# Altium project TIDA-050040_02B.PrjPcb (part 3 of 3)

## Sheet TIDA-050040_PwrSupplies.SchDoc: MCU Power 2
size 431 x 279 mm; Date: Not shown in title block; ApprovedBy: Not shown in title block; CheckedBy: Not shown in title block; Author: Not shown in title block; CompanyName: Not shown in title block; DrawnBy: Kerry Murphy; Engineer: Not shown in title block; Organization: Not shown in title block; Address1: Not shown in title block; Address2: Not shown in title block; Address3: Not shown in title block; Address4: Not shown in title block; DocumentNumber: 9; Revision: Use project parameter SCH_Rev; SheetNumber: 9; SheetTotal: 10; PageSetup: Record=PageOptions¦CenterHorizontal=True¦CenterVertical=True¦PrintScale=1.00¦XCorrection=1.00¦YCorrection=1.00¦PrintKind=0¦BorderSize=5000000¦LeftOffset=0¦BottomOffset=0¦Orientation=2¦PaperLength=1000¦PaperWidth=1000¦Scale=100¦PaperSource=15¦PrintQuality=600¦MediaType=1¦DitherType=10¦PaperKind=Letter¦PrintScaleMode=1
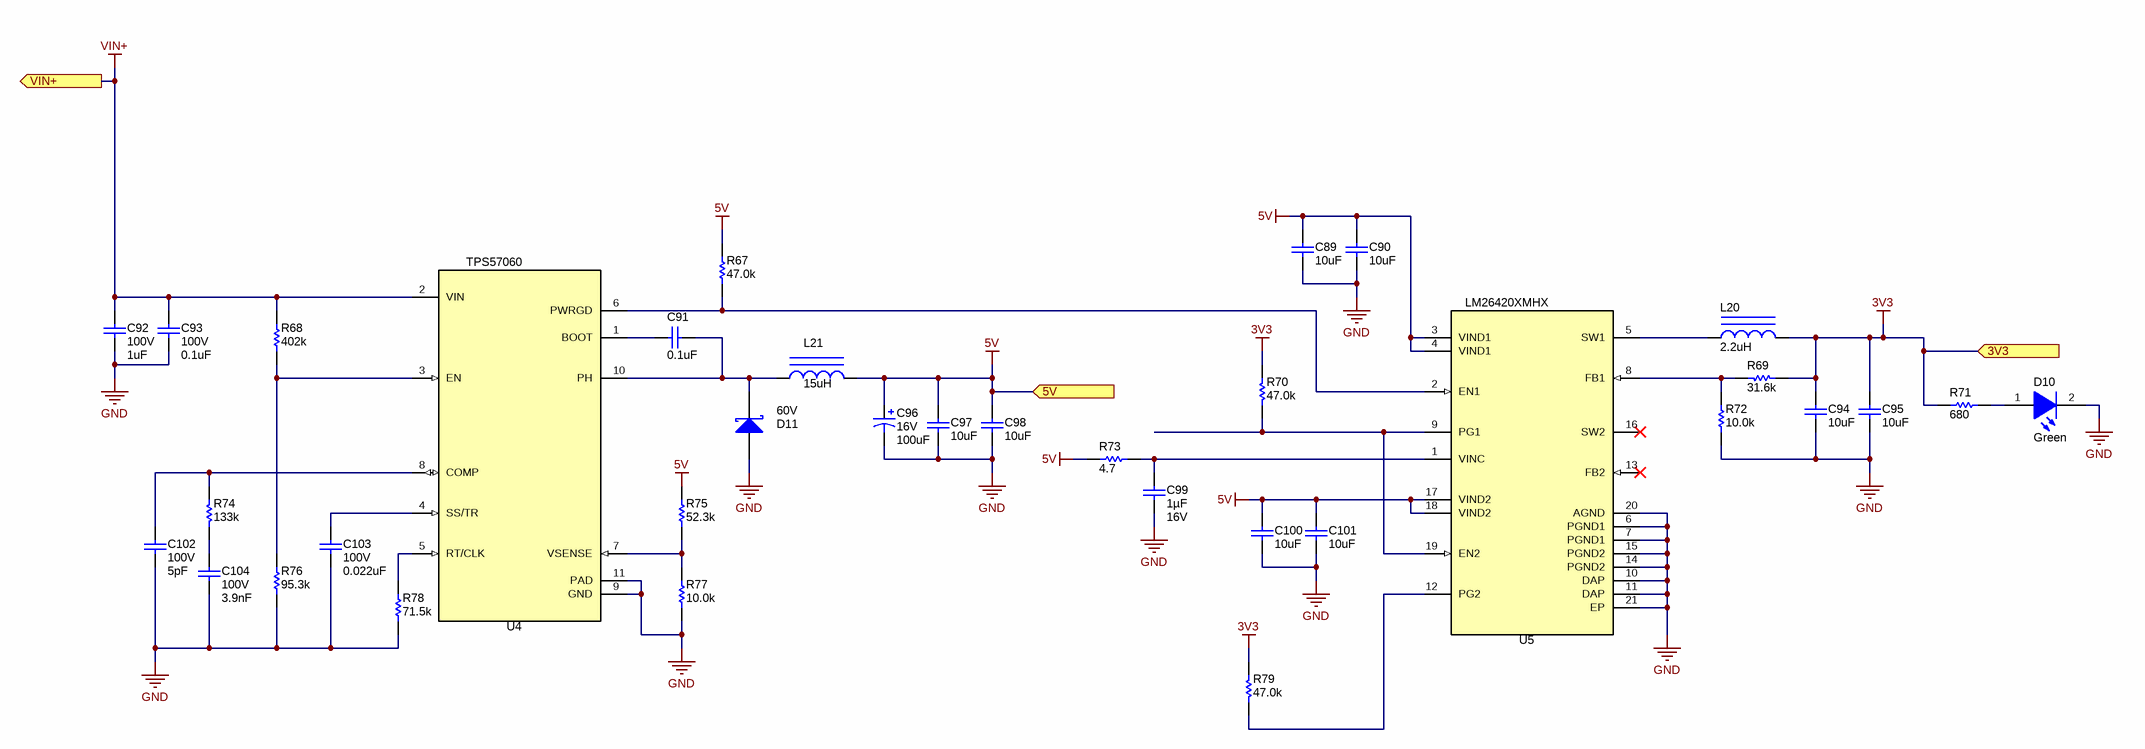
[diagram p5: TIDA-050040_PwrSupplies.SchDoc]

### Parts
C89  ValueDisplayed: 10uF  [1206_180]  (hidden comment: Capacitor)
C90  ValueDisplayed: 10uF  [1206_180]  (hidden comment: Capacitor)
C91  ValueDisplayed: 0.1uF  [0603_HV]  (hidden comment: Capacitor)
C92  VDC_V: 100V  ValueDisplayed: 1uF  [0805_HV]  (hidden comment: CGA4J3X7S2A105K125AB)
C93  VDC_V: 100V  ValueDisplayed: 0.1uF  [0805_HV]  (hidden comment: CGA4J2X7R2A104K125AA)
C94  ValueDisplayed: 10uF  [1206_180]  (hidden comment: Capacitor)
C95  ValueDisplayed: 10uF  [1206_180]  (hidden comment: Capacitor)
C96  VDC_V: 16V  ValueDisplayed: 100uF  [SM_RADIAL_D]  (hidden comment: EEEFP1C101AP)
C97  ValueDisplayed: 10uF  [1206_180]  (hidden comment: Capacitor)
C98  ValueDisplayed: 10uF  [1206_180]  (hidden comment: Capacitor)
C99  Cap_F: 1µF  VDC_V: 16V  [0603]  (hidden comment: EMK107B7105KAHT)
C100  ValueDisplayed: 10uF  [1206_180]  (hidden comment: Capacitor)
C101  ValueDisplayed: 10uF  [1206_180]  (hidden comment: Capacitor)
C102  VDC_V: 100V  ValueDisplayed: 5pF  [0402]  (hidden comment: GRM1555C2A5R0CA01D)
C103  VDC_V: 100V  ValueDisplayed: 0.022uF  [0603]  (hidden comment: CGA3E2X7R2A223K080AA)
C104  VDC_V: 100V  Cap_F: 3.9nF  [0603]  (hidden comment: 06031C392JAT2A)
D10  value Green  [LG_R971_Green]  (hidden comment: LED)
D11  value 60V  [SMA]  (hidden comment: DIODE_SCHOTTKY)
L20  ValueDisplayed: 2.2uH  [LPS3010]  (hidden comment: LPS3010-222MLB)
L21  ValueDisplayed: 15uH  [XAL4040]  (hidden comment: Inductor_Iron)
R67  ValueDisplayed: 47.0k  [0603_HV]  (hidden comment: Resistor)
R68  ValueDisplayed: 402k  [0603]  (hidden comment: ERJ-3EKF4023V)
R69  ValueDisplayed: 31.6k  [0603_HV]  (hidden comment: Resistor)
R70  ValueDisplayed: 47.0k  [0603_HV]  (hidden comment: Resistor)
R71  ValueDisplayed: 680  [0603_HV]  (hidden comment: Resistor)
R72  ValueDisplayed: 10.0k  [0603_HV]  (hidden comment: Resistor)
R73  ValueDisplayed: 4.7  [0603_HV]  (hidden comment: Resistor)
R74  ValueDisplayed: 133k  [0603_HV]  (hidden comment: Resistor)
R75  ValueDisplayed: 52.3k  [0603_HV]  (hidden comment: Resistor)
R76  ValueDisplayed: 95.3k  [0603_HV]  (hidden comment: Resistor)
R77  ValueDisplayed: 10.0k  [0603_HV]  (hidden comment: Resistor)
R78  ValueDisplayed: 71.5k  [0603]  (hidden comment: CRCW060371K5FKEA)
R79  ValueDisplayed: 47.0k  [0603_HV]  (hidden comment: Resistor)
U4  TPS57060  [DGQ0010D_N]
U5  LM26420XMHX  [PWP0020A_N]

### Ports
3V3, 5V, VIN+

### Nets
3V3: C94.1 C95.1 L20.2 R69.1 R70.2 R71.2 R79.2 ; port 3V3
5V: C89.1 C90.1 C96.1(+) C97.1 C98.1 C100.1 C101.1 L21.2 R67.2 R73.1 R75.2 U5.3(VIND1) U5.4(VIND1) U5.17(VIND2) U5.18(VIND2) ; port 5V
GND: C89.2 C90.2 C92.2 C93.2 C94.2 C95.2 C96.2(-) C97.2 C98.2 C99.2 C100.2 C101.2 C102.2 C103.2 C104.2 D10.2(K) D11.2(A) R72.1 R76.1 R77.1 R78.1 U4.9(GND) U4.11(PAD) U5.6(PGND1) U5.7(PGND1) U5.10(DAP) U5.11(DAP) U5.14(PGND2) U5.15(PGND2) U5.20(AGND) U5.21(EP)
VIN+: C92.1 C93.1 R68.2 U4.2(VIN) ; port VIN+  [project net VIN]
NetC91_1: C91.1 U4.1(BOOT)
NetC91_2: C91.2 D11.1(K) L21.1 U4.10(PH)
NetC99_1: C99.1 R73.2 U5.1(VINC)
NetC102_1: C102.1 R74.2 U4.8(COMP)
NetC103_1: C103.1 U4.4(SS/TR)
NetC104_1: C104.1 R74.1
NetD10_1: D10.1(A) R71.1
NetL20_1: L20.1 U5.5(SW1)
NetR67_1: R67.1 U4.6(PWRGD) U5.2(EN1)
NetR68_1: R68.1 R76.2 U4.3(EN)
NetR69_2: R69.2 R72.2 U5.8(FB1)
NetR70_1: R70.1 U5.9(PG1) U5.19(EN2)
NetR75_1: R75.1 R77.2 U4.7(VSENSE)
NetR78_2: R78.2 U4.5(RT/CLK)
NetR79_1: R79.1 U5.12(PG2)

Not connected (* = marked no-connect by the designer): U5 13(FB2)* 16(SW2)*

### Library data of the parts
C89 C90 C94 C95 C97 C98 C100 C101 = CMP-0008965-2: CAP, CERM, 10 uF, 25 V, +/- 10%, X7R, 1206; PartNumber: GRM31CR71E106KA12L; Manufacturer: MuRata; Polarized: N; Value: 10uF; U/M: EA; Cap_F: 10µF; Value1: Unknown; VDC_V: 25V; TaMin_C: -55°C; TaMax_C: 125°C; Cap_Case: 2220; SizeArea_mm2: 5.12; SizeAreaWB_mm2: 10.92; SizeX_mm: 3.2; SizeY_mm: 1.6; SizeZ_mm: 1.8; AEC Category: Q200
C91 = CMP-0007469-4: CAP, CERM, 0.1 uF, 100 V, +/- 10%, X7R, 0603; PartNumber: GRM188R72A104KA35D; Manufacturer: MuRata; Polarized: N; Value: 0.1uF; U/M: EA; Cap_F: 100nF; Value1: Unknown; VDC_V: 100V; TaMin_C: -55°C; TaMax_C: 125°C; Cap_Case: 0603; SizeArea_mm2: 1.28; SizeAreaWB_mm2: 4.68; SizeX_mm: 1.6; SizeY_mm: 0.8; SizeZ_mm: 1; AEC Category: Q200
C92 = CMP-0007980-2: CAP, CERM, 1 uF, 100 V, +/- 10%, X7S, AEC-Q200 Grade 1, 0805; Manufacturer: TDK; TaMin_C: -55°C; ESR_ohm: 8.255m; Polarized: N; SizeAreaWB_mm2: 6.75; Value1: 0.008255 ohm; U/M: EA; Value: 1uF; TaMax_C: 125°C; SizeZ_mm: 1.45; SizeX_mm: 2; SizeY_mm: 1.25; Cap_Case: 0805; SizeArea_mm2: 2.5; AEC Qualified: Y; Cap_F: 1µF; IRMS_A: 2.27442A; AEC Grade: 1; AEC Category: Q200
C93 = CMP-0007969-2: CAP, CERM, 0.1 uF, 100 V, +/- 10%, X7R, AEC-Q200 Grade 1, 0805; Manufacturer: TDK; TaMin_C: -55°C; ESR_ohm: 0.020726; Polarized: N; SizeAreaWB_mm2: 6.75; Value1: 0.020726 ohm; U/M: EA; Value: 0.1uF; TaMax_C: 125°C; SizeZ_mm: 1.45; SizeX_mm: 2; SizeY_mm: 1.25; Cap_Case: 0805; SizeArea_mm2: 2.5; CompType: Capacitor; AEC Qualified: Y; Cap_F: 100nF; IRMS_A: 1.456A; AEC Grade: 1; AEC Category: Q200
C96 = CMP-0010733-1: CAP, AL, 100 uF, 16 V, +/- 20%, 0.26 ohm, AEC-Q200 Grade 2, SMD; Manufacturer: Panasonic; TaMin_C: -55°C; ESR_ohm: 2.6d; Polarized: Y; SizeAreaWB_mm2: 84.28; U/M: EA; Value: 100uF; TaMax_C: 125°C; SizeZ_mm: 5.4; SizeX_mm: 7.8; SizeY_mm: 6.6; Cap_Case: D; SizeArea_mm2: 51.48; CompType: Capacitor; Cap_F: 100µF; AEC Grade: 2; AEC Category: Q200
C99 = CMP-0080104-1: CAP, CERM, 1 µF, 16 V,+/- 10%, X7R, AEC-Q200 Grade 1, 0603; Manufacturer: Taiyo Yuden; SizeAreaWB_mm2: 4.68; SizeArea_mm2: 1.28; AEC Qualified: Y; AEC Category: Q200; Value: 1uF; TaMax_C: 125°C; SizeZ_mm: 1; Polarized: N; TaMin_C: -55°C; SizeY_mm: 0.8; U/M: EA; CompType: Capacitor; SizeX_mm: 1.6
C102 = CMP-0006503-2: CAP, CERM, 5 pF, 100 V, +/- 5%, C0G/NP0, 0402; Manufacturer: MuRata; TaMin_C: -55°C; Polarized: N; SizeAreaWB_mm2: 3; Value1: Unknown; U/M: EA; Value: 5pF; TaMax_C: 125°C; SizeZ_mm: 0.6; SizeX_mm: 1; SizeY_mm: 0.5; AEC Category: Q200
C103 = CMP-0007086-4: CAP, CERM, 0.022 uF, 100 V, +/- 10%, X7R, AEC-Q200 Grade 1, 0603; Manufacturer: TDK; TaMin_C: -55°C; ESR_ohm: 0.083542; Polarized: N; SizeAreaWB_mm2: 4.68; Value1: 0.083542 ohm; U/M: EA; TaMax_C: 125°C; SizeZ_mm: 1; SizeX_mm: 1.6; SizeY_mm: 0.8; SizeArea_mm2: 1.28; AEC Qualified: Y; Cap_F: 22nF; IRMS_A: 6.09312dA; AEC Category: Q200
C104 = CMP-0860984-1: CAP, CERM, 3900 pF, 100 V,+/- 5%, X7R, 0603; Manufacturer: AVX; SizeArea_mm2: 1.28; TaMin_C: -55°C; ValueDisplayed: 3900pF; Polarized: N; SizeX_mm: 1.6; SizeAreaWB_mm2: 4.68; U/M: EA; Value: 3900pF; CompType: Capacitor; AEC Category: Q200; SizeZ_mm: 1; SizeY_mm: 0.8; TaMax_C: 125°C
D10 = CMP-0002980-3: LED, Green, SMD; PartNumber: LG R971-KN-1; Manufacturer: OSRAM; Vf_V: 2.2V; Io_A: 20mA; Vr_V: 12V; Ir_A: 100µA; Tjmax_C: 95°C; Value1: W; Angle: 160
D11 = CMP-0028837-2: Diode, Schottky, 60 V, 2 A, AEC-Q101, SMA; PartNumber: SS26SHE3_A/H; Manufacturer: Vishay-Semiconductor; Vf_V: 7.5dV; Value1: 2A; Value2: 0.75V; TJmax_C: 150°C; SizeAreaWB_mm2: 37.3428; SizeArea_mm2: 16.3228; SizeX_mm: 5.59; SizeY_mm: 2.92; SizeZ_mm: 2.87; AEC Category: Q101; AEC Qualified: Y; Green_Lifecycle: Not Set; Green_REACh: Incomplete
L20 = CMP-0060436-1: Inductor, Shielded Drum Core, Ferrite, 2.2 uH, 1.1 A, 0.22 ohm, SMD; Manufacturer: Coilcraft; Isat: 1.4A @ 30% inductance drop; Irms: 1.1A @ 40C rise; Green_Lifecycle: Not Set; SizeAreaWB_mm2: 15.6025; DCR_ohm: 2.2d; Green_REACh: Incomplete; Value: 2.2uH; Imax_A: 1.1A; SizeZ_mm: 0.9; SizeX_mm: 2.95; SizeArea_mm2: 8.7025; Ind_H: 2.2µH; AEC Category: Q200
L21 = CMP-0061649-2: Inductor, Shielded, Composite, 15 uH, 2.8 A, 0.109 ohm, SMD; PartNumber: XAL4040-153MEB; Manufacturer: Coilcraft; Value: 15uH; Ind_H: 15µH; Imax_A: 2.8A; Irms: 2.8A @ 40C rise; Isat: 2.8A @ 30% inductance drop; DCR_ohm: 1.09d; AEC Category: Q200; Green_Lifecycle: Not Set; Green_REACh: Incomplete; SizeArea_mm2: 16; SizeAreaWB_mm2: 25; SizeX_mm: 4; SizeZ_mm: 4.1
R67 R70 R79 = CMP-0023133-5: RES, 47.0 k, 1%, 0.1 W, 0603; PartNumber: RC0603FR-0747KL; Manufacturer: Yageo; Value: 47.0k; Res_ohm: 47k; Value_Code: 47k0; Power_W: 100mW; Value2: 0.1W; VDC_V: 75V; TempCo: 100 ppm/C; AEC Category: Q200; AEC Qualified: N; SizeArea_mm2: 1.28; SizeAreaWB_mm2: 4.68; SizeX_mm: 1.6; SizeY_mm: 0.8; SizeZ_mm: 1
R68 = CMP-0022701-2: RES, 402 k, 1%, 0.1 W, AEC-Q200 Grade 0, 0603; Manufacturer: Panasonic; Power_W: 100mW; TempCo: 100 ppm/C; U/M: EA; Value: 402k; EIA_Code: E96; SizeX_mm: 1.6; SizeY_mm: 0.8; SizeZ_mm: 1; Value2: 0.1W; SizeArea_mm2: 1.28; CompType: Resistor; AEC Qualified: Y; VDC_V: 50V; AEC Grade: 0; AEC Category: Q200
R69 = CMP-0023026-5: RES, 31.6 k, 1%, 0.1 W, 0603; PartNumber: RC0603FR-0731K6L; Manufacturer: Yageo; Value: 31.6k; Value_Code: 31k6; Power_W: 100mW; Value2: 0.1W; VDC_V: 75V; TempCo: 100 ppm/C; EIA_Code: E96; AEC Category: Q200; AEC Qualified: N; SizeArea_mm2: 1.28; SizeAreaWB_mm2: 4.68; SizeX_mm: 1.6; SizeY_mm: 0.8; SizeZ_mm: 1
R71 = CMP-0023235-5: RES, 680, 1%, 0.1 W, 0603; PartNumber: RC0603FR-07680RL; Manufacturer: Yageo; Value: 680; Value_Code: 680R; Power_W: 100mW; Value2: 0.1W; VDC_V: 75V; TempCo: 100 ppm/C; AEC Category: Q200; AEC Qualified: N; SizeArea_mm2: 1.28; SizeAreaWB_mm2: 4.68; SizeX_mm: 1.6; SizeY_mm: 0.8; SizeZ_mm: 1
R72 R77 = CMP-0021998-4: RES, 10.0 k, 1%, 0.1 W, AEC-Q200 Grade 0, 0603; PartNumber: CRCW060310K0FKEA; Manufacturer: Vishay-Dale; Value: 10.0k; Res_ohm: 10k; Value_Code: 10k0; Power_W: 100mW; Value2: 0.1W; VDC_V: 75V; TempCo: 100 ppm/C; EIA_Code: E96; AEC Category: Q200; AEC Qualified: Y; AEC Grade: 0; SizeArea_mm2: 1.28; SizeX_mm: 1.6; SizeY_mm: 0.8; SizeZ_mm: 1
R73 = CMP-0025821-4: RES, 4.7, 5%, 0.1 W, AEC-Q200 Grade 0, 0603; PartNumber: CRCW06034R70JNEA; Manufacturer: Vishay-Dale; Value: 4.7; Value_Code: 4R70; Power_W: 100mW; Value2: 0.1W; VDC_V: 75V; TempCo: 200 ppm/C; EIA_Code: E24; AEC Category: Q200; AEC Qualified: Y; AEC Grade: 0; SizeArea_mm2: 1.28; SizeX_mm: 1.6; SizeY_mm: 0.8; SizeZ_mm: 1
R74 = CMP-0022038-4: RES, 133 k, 1%, 0.1 W, AEC-Q200 Grade 0, 0603; PartNumber: CRCW0603133KFKEA; Manufacturer: Vishay-Dale; Value: 133k; Power_W: 100mW; Value2: 0.1W; VDC_V: 75V; TempCo: 100 ppm/C; EIA_Code: E96; AEC Category: Q200; AEC Qualified: Y; AEC Grade: 0; SizeArea_mm2: 1.28; SizeX_mm: 1.6; SizeY_mm: 0.8; SizeZ_mm: 1
R75 = CMP-0022486-4: RES, 52.3 k, 1%, 0.1 W, AEC-Q200 Grade 0, 0603; PartNumber: CRCW060352K3FKEA; Manufacturer: Vishay-Dale; Value: 52.3k; Value_Code: 52k3; Power_W: 100mW; Value2: 0.1W; VDC_V: 75V; TempCo: 100 ppm/C; EIA_Code: E96; AEC Category: Q200; AEC Qualified: Y; AEC Grade: 0; SizeArea_mm2: 1.28; SizeX_mm: 1.6; SizeY_mm: 0.8; SizeZ_mm: 1
R76 = CMP-0022659-4: RES, 95.3 k, 1%, 0.1 W, AEC-Q200 Grade 0, 0603; PartNumber: CRCW060395K3FKEA; Manufacturer: Vishay-Dale; Value: 95.3k; Value_Code: 95k3; Power_W: 100mW; Value2: 0.1W; VDC_V: 75V; TempCo: 100 ppm/C; EIA_Code: E96; AEC Category: Q200; AEC Qualified: Y; AEC Grade: 0; SizeArea_mm2: 1.28; SizeX_mm: 1.6; SizeY_mm: 0.8; SizeZ_mm: 1
R78 = CMP-0022581-4: RES, 71.5 k, 1%, 0.1 W, AEC-Q200 Grade 0, 0603; Manufacturer: Vishay-Dale; Power_W: 100mW; TempCo: 100 ppm/C; Value_Code: 71k5; Value: 71.5k; EIA_Code: E96; SizeX_mm: 1.6; SizeY_mm: 0.8; SizeZ_mm: 1; Value2: 0.1W; SizeArea_mm2: 1.28; AEC Qualified: Y; VDC_V: 75V; AEC Category: Q200; AEC Grade: 0
U4 = CMP-0074018-2: Automotive 3.5V to 60V, 1.5A Step Down SWIFT(TM) Converter with Eco-Mode(TM), DGQ0010D (VSSOP-10); PartNumber: TPS57160QDGQRQ1; Manufacturer: Texas Instruments; SizeArea_mm2: 14.7; SizeAreaWB_mm2: 23.6; SizeX_mm: 4.9; SizeY_mm: 3.0; SizeZ_mm: 1.1; CompType: IC; U/M: EA; AEC Category: Q200; AEC Qualified: Y
U5 = CMP-0066062-3: Dual 2.0A, High Frequency Synchronous Step-Down DC-DC  Regulator, PWP0020A (HTSSOP-20); PartNumber: LM26420Q0XMHX/NOPB; Alternate PartNumber: LM26420Q0XMH/NOPB; Manufacturer: Texas Instruments; SizeArea_mm2: 41.6; SizeAreaWB_mm2: 71.4; SizeX_mm: 6.4; SizeY_mm: 6.5; SizeZ_mm: 1.2; CompType: IC; AEC Category: Q200; AEC Qualified: Y; Rating: Automotive

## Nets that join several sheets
3V3: TIDA-050040_MSP432E4x (L22.1 L23.1), TIDA-050040_PwrSupplies (7 pins)
5V: BOOST- SEPIC (R107.1), Buck (Q4.2 R34.2 R46.2 R49.2), TIDA-050040_Battery (R134.2), TIDA-050040_PwrSupplies (15 pins)
GND: BOOST- SEPIC (53 pins), Buck (33 pins), TIDA-050040_Battery (58 pins), TIDA-050040_MSP432E4x (49 pins), TIDA-050040_PwrSupplies (31 pins)
MCU_3V3D: BOOST- SEPIC (R16.2 R17.2 R20.2), TIDA-050040_Battery (6 pins), TIDA-050040_MSP432E4x (35 pins)
VBST: BOOST- SEPIC (11 pins), Buck (8 pins)
VIN: BOOST- SEPIC (12 pins), TIDA-050040_Battery (C78.1 C79.1 C80.1 L10.2), TIDA-050040_MSP432E4x (D21.2), TIDA-050040_PwrSupplies (C92.1 C93.1 R68.2 U4.2)
A_NTC1: BOOST- SEPIC (R20.1 RT1.2), TIDA-050040_MSP432E4x (C127.1 U10.21)
BPWM1: BOOST- SEPIC (R16.1 U1.3), TIDA-050040_MSP432E4x (R91.2)
BUCK_nFLT_1-2: Buck (U2.22), TIDA-050040_MSP432E4x (R105.1 R108.2)
DRL_NTC: TIDA-050040_Battery (R141.1 R143.2), TIDA-050040_MSP432E4x (C126.1 U10.20)
DRLPOS+: BOOST- SEPIC (5 pins), TIDA-050040_Battery (C134.1 L9.1)
DRLPOS_MICRO: BOOST- SEPIC (R90.1), TIDA-050040_Battery (D16.1 R114.2 R118.2), TIDA-050040_MSP432E4x (U10.104)
DRLPOSPWM: BOOST- SEPIC (R17.1 R90.2 R107.2 U1.4), TIDA-050040_MSP432E4x (R92.2)
HB_DRIVE_MICRO: TIDA-050040_Battery (Q10.1), TIDA-050040_MSP432E4x (U10.49)
HB_MICRO: TIDA-050040_Battery (D9.1 R56.2 R60.2), TIDA-050040_MSP432E4x (U10.103)
LB_FAULT_MICRO: TIDA-050040_Battery (R129.2), TIDA-050040_MSP432E4x (U10.5)
LB_MICRO: Buck (R28.1), TIDA-050040_Battery (D8.1 R54.2 R58.2), TIDA-050040_MSP432E4x (U10.118)
LB_NTC: TIDA-050040_Battery (R136.1 R139.2), TIDA-050040_MSP432E4x (C124.1 U10.18)
LBHB+: Buck (6 pins), TIDA-050040_Battery (C86.1 L2.1)
LBHBPWM: Buck (R51.1), TIDA-050040_MSP432E4x (U10.44)
MISOM: BOOST- SEPIC (U1.7), Buck (U2.26), TIDA-050040_MSP432E4x (R93.1 U10.1)
MOSIM: BOOST- SEPIC (U1.8), Buck (U2.27), TIDA-050040_MSP432E4x (U10.2)
PD3: BOOST- SEPIC (U1.6), Buck (U2.25), TIDA-050040_MSP432E4x (U10.4)
PD5: TIDA-050040_Battery (R135.1 R138.2), TIDA-050040_MSP432E4x (C130.1 U10.126)
PD6: TIDA-050040_Battery (R130.1 R132.2), TIDA-050040_MSP432E4x (C129.1 U10.127)
PD7: TIDA-050040_Battery (R140.1 R142.2), TIDA-050040_MSP432E4x (C128.1 U10.128)
PE0: Buck (R40.1 R41.2), TIDA-050040_MSP432E4x (C116.1 U10.15)
PE1: Buck (R38.1 R39.2), TIDA-050040_MSP432E4x (C117.1 U10.14)
PE2: BOOST- SEPIC (R21.1 R23.2), TIDA-050040_MSP432E4x (C118.1 U10.13)
PE3: BOOST- SEPIC (R5.1 R7.2), TIDA-050040_MSP432E4x (C131.1 U10.12)
PE4: BOOST- SEPIC (R8.1 R13.2), TIDA-050040_MSP432E4x (C132.1 U10.123)
PL4: Buck (R48.2), TIDA-050040_MSP432E4x (U10.85)
PM1: BOOST- SEPIC (U1.11), TIDA-050040_MSP432E4x (R102.1 U10.77)
PM2: BOOST- SEPIC (U1.10), TIDA-050040_MSP432E4x (R103.1 U10.76)
SSN_BOOST: BOOST- SEPIC (U1.5), TIDA-050040_MSP432E4x (R109.1)
SSN_BUCK_1-2: Buck (R43.2), TIDA-050040_MSP432E4x (R110.1)
TI+: Buck (6 pins), TIDA-050040_Battery (C133.1 L6.1)
TI_FAULT_MICRO: TIDA-050040_Battery (R125.2), TIDA-050040_MSP432E4x (U10.6)
TI_MICRO: Buck (R15.1), TIDA-050040_Battery (D15.1 R112.2 R116.2), TIDA-050040_MSP432E4x (U10.119)
TIND_NTC: TIDA-050040_Battery (R131.1 R133.2), TIDA-050040_MSP432E4x (C125.1 U10.19)
TIPWM: Buck (R36.1), TIDA-050040_MSP432E4x (U10.45)

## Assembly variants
001: not fitted FID1 FID2 FID3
